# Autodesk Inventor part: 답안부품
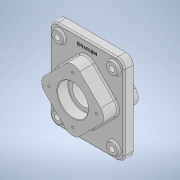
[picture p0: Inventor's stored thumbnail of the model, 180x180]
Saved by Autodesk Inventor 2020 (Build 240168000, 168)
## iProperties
Created: 2021-07
Part Number: 답안부품
Material: 일반
Document SubType Name: Modeling
Designer: Owner
Density: 1 g/cm^3
Appearance: 기본값
Mass: 807.977 g
Surface Area: 961.758 cm^2
Volume: 807.977 cm^3
Author: Owner
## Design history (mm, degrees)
sketch "스케치1"
  geometry: L1 (-75, -90)-(75, -90); L2 (75, -90)-(75, 90); L3 (75, 90)-(-75, 90); L4 (-75, 90)-(-75, -90); L5 (-75, -90)-(75, 90); L6 (75, -90)-(-75, 90); 1 further point
  constraints: 12 end point, 2 midpoint, 2 parallel, 1 horizontal, 1 perpendicular
  dimensions: "d0" = 150 distance of L3.end L2.end; "d1" = 180 distance of L2.end L1.end
extrude "돌출1" new body sketch "스케치1" stored distance "d2" = 18; taper "d3" = 0 deg
sketch "스케치2"
  geometry: L1 (-70.711, 0)-(0, 70.711); L2 (0, 70.711)-(70.711, 0); L3 (70.711, 0)-(0, -70.711); L4 (0, -70.711)-(-70.711, 0); L5 (-70.711, 0)-(70.711, 0); L6 (0, 70.711)-(0, -70.711); 2 further points
  constraints: 12 end point, 3 midpoint, 2 parallel, 1 perpendicular, 1 vertical alignment
  dimensions: "d4" = 100 distance of L1.end L2.end; "d5" = 100 distance of L1.start L1.end
extrude "돌출2" join sketch "스케치2" distance "d6" = 38; taper "d7" = 0 deg; dims "d25" = 32, "d26" = 0
fillet "모깎기1" dims "d8" = 20
fillet "모깎기2" dims "d9" = 3
fillet "모깎기3" dims "d10" = 15
fillet "모깎기4" dims "d27" = 3
sketch "스케치5"
  geometry: C1 r 31 at (0, 0); 1 further point
  constraints: 1 centre point, 1 coincident
  dimensions: "d28" = 62 diameter of C1
hole "구멍3" sketch "스케치5" at (0, 0) diameter "d29" = 45; stored, may be unused: countersink angle "d33" = 90 deg, drill point angle "d35" = 118 deg; dims "d30" = 6, "d31" = 62, "d32" = 22, "d34" = 8
sketch "스케치6"
  geometry: C1 r 22.5 at (0, 0) reference; 2 further points
  constraints: 1 coincident
hole "구멍4" sketch "스케치6" at (0, 0) diameter "d36" = 45; stored, may be unused: countersink angle "d40" = 90 deg, drill point angle "d42" = 118 deg; dims "d37" = 6, "d38" = 62, "d39" = 22, "d41" = 8
fillet "모깎기5" dims "d50" = 1
sketch "스케치8"
  geometry: C1 r 11 at (-55, 70); C2 r 11 at (55, 70); 1 further point
  constraints: 2 centre point, 1 horizontal alignment
  dimensions: "d51" = 22 diameter of C1; "d52" = 22 diameter of C2; "d53" = 110 distance of C2.centre C1.centre; "d54" = 55 horizontal distance of point (0, 0) C1.centre; "d55" = 70 vertical distance of point (0, 0) C1.centre
extrude "돌출3" join sketch "스케치8" distance "d56" = 5; taper "d57" = 0 deg
sketch "스케치9"
  geometry: C1 r 11 at (0, 0) reference; 2 further points
  constraints: 1 coincident
hole "구멍6" sketch "스케치9" at (0, 0) diameter "d58" = 11; stored, may be unused: countersink angle "d62" = 90 deg, drill point angle "d64" = 118 deg; dims "d59" = 12, "d60" = 62, "d61" = 22, "d63" = 17.1
fillet "모깎기6" dims "d65" = 3
sketch "스케치10" dims "d66" = 96
  geometry: C1 r 22.5 at (0, 0) reference; 3 further points
  constraints: 1 coincident, 1 vertical alignment, 2 other
hole "구멍7" sketch "스케치10" at (0, 48) diameter "d67" = 4.917; stored, may be unused: countersink angle "d71" = 90 deg, drill point angle "d73" = 118 deg; dims "d68" = 10, "d69" = 62, "d70" = 22, "d72" = 13
sketch "스케치11" dims "d78" = 96
  geometry: C1 r 22.5 at (0, 0) reference; 3 further points
  constraints: 1 coincident, 1 vertical alignment, 2 other
hole "구멍8" sketch "스케치11" at (0, 48) diameter "d79" = 4.917; stored, may be unused: countersink angle "d83" = 90 deg, drill point angle "d85" = 118 deg; dims "d80" = 10, "d81" = 62, "d82" = 22, "d84" = 13
sketch "스케치12"
  geometry: L1 (60, 90)-(-60, 90) reference; 2 further points
  constraints: 1 vertical alignment, 1 other
  dimensions: "d89" = 15 distance from line of point (0, 75) L1
feature "엠보싱1" sketch "스케치12" dims "d0" = 150, "d1" = 180, "d9" = 3, "d90" = 0.5, "d91" = 0
chamfer "모따기1" distance "d92" = 1; stored, may be unused: second distance "d93" = 2, angle "d94" = 45 deg
node "솔리드1"
mirror "미러4"
mirror "미러5"
pattern_circular "원형 패턴1" dims angle "d75" = 360 deg
pattern_circular "원형 패턴2" dims angle "d87" = 360 deg
feature "A9D066F2-1C7D-4E18-AEED-F7BC21143FA4" dims "d29" = 45, "d30" = 6, "d31" = 62, "d32" = 22, "d33" = 90 deg, "d34" = 8, "d35" = 118 deg
